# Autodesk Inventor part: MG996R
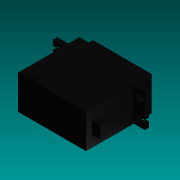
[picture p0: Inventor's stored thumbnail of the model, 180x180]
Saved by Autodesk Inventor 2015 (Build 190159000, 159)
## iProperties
Created: 2016-02
Part Number: MG996R
Material: Generic
Document SubType Name: Modeling
Designer: Rafał
Density: 1 g/cm^3
Appearance: Smooth - Black
Author: Rafał
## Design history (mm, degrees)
sketch "Sketch1"
  geometry: L1 (0, 0)-(40, 0); L2 (40, 0)-(40, 27.5); L3 (40, 27.5)-(47, 27.5); L4 (47, 27.5)-(47, 30); L5 (47, 30)-(40, 30); L6 (40, 30)-(40, 38.5); L7 (40, 38.5)-(5.5, 38.5); L8 (5.5, 38.5)-(5.5, 36); L9 (5.5, 36)-(0, 36); L10 (0, 36)-(0, 30); L11 (0, 30)-(-7, 30); L12 (-7, 30)-(-7, 27.5); L13 (-7, 27.5)-(0, 27.5); L14 (0, 27.5)-(0, 0)
  constraints: 28 end point, 8 perpendicular, 7 point on line, 2 vertical, 1 horizontal
  dimensions: "d0" = 40 distance of L1.start L1.end; "d1" = 27.5 distance of L1.end L2.end; "d2" = 7 distance of L2.end L3.end; "d3" = 2.5 distance of L3.end L4.end; "d4" = 8.5 distance of L5.end L6.end; "d5" = 34.5 distance of L6.end L7.end; "d6" = 2.5 distance of L7.end L8.end; "d7" = 7 distance of L10.end L11.end
extrude "Extrusion1" new body sketch "Sketch1" distance "d8" = 20; taper "d9" = 0 deg
sketch "Sketch2"
  geometry: L1 (7, 0)-(0, 0) reference; L2 (0, 0)-(0, -20) reference; L3 (0, 0)-(0, -20) reference; L4 (3.6, -4.6)-(0, -4.6); L5 (0, -4.6)-(0, -3.6); L6 (0, -3.6)-(3.6, -3.6); L7 (3.6, -3.6)-(3.6, -4.6); L8 (3.6, -4.6)-(0, -4.6); L9 (0, -4.6)-(0, -5.6); L10 (0, -5.6)-(3.6, -5.6); L11 (3.6, -5.6)-(3.6, -4.6); L12 (0, -10)-(54, -10); L13 (54, 0)-(54, -20) reference; L14 (27, -10)-(27, -2.45); L15 (7, 0)-(7, -20) reference; L16 (0, 0)-(7, 0); L17 (7, 0)-(7, -0.5); L18 (7, -0.5)-(0, -0.5); L19 (0, -0.5)-(0, 0); L20 (0, -14.4)-(3.6, -14.4); L21 (3.6, -14.4)-(3.6, -15.4); L22 (3.6, -16.4)-(3.6, -15.4); L23 (0, -16.4)-(3.6, -16.4); L24 (0, -15.4)-(0, -16.4); L25 (0, -15.4)-(0, -14.4); L26 (3.6, -15.4)-(0, -15.4); L27 (7, -20)-(0, -20); L28 (7, -19.5)-(0, -19.5); L29 (7, -20)-(7, -19.5); L30 (7, -20)-(7, 0); L31 (0, -19.5)-(0, -20); L32 (7, 0)-(7, -0.5); L33 (7, -19.5)-(7, -20); L34 (50.4, -14.4)-(50.4, -15.4); L35 (50.4, -16.4)-(50.4, -15.4); L36 (54, -14.4)-(50.4, -14.4); L37 (50.4, -15.4)-(54, -15.4); L38 (54, -15.4)-(54, -14.4); L39 (54, -16.4)-(50.4, -16.4); L40 (54, -15.4)-(54, -16.4); L41 (54, -19.5)-(54, -20); L42 (47, -19.5)-(54, -19.5); L43 (47, -20)-(54, -20); L44 (47, 0)-(54, 0); L45 (54, 0)-(54, -20); L46 (54, 0)-(54, -20); L47 (47, 0)-(47, -20); L48 (47, -20)-(47, 0); L49 (47, -19.5)-(47, -20); L50 (47, -20)-(47, -19.5); L51 (50.4, -4.6)-(54, -4.6); L52 (54, -4.6)-(54, -3.6); L53 (54, -3.6)-(50.4, -3.6); L54 (50.4, -3.6)-(50.4, -4.6); L55 (54, -5.6)-(50.4, -5.6); L56 (50.4, -4.6)-(54, -4.6); L57 (54, -4.6)-(54, -5.6); L58 (50.4, -5.6)-(50.4, -4.6); L59 (47, -0.5)-(54, -0.5); L60 (54, 0)-(47, 0); L61 (47, 0)-(47, -0.5); L62 (47, 0)-(47, -0.5); L63 (54, -0.5)-(54, 0); L64 (3.6, -16.4)-(0, -16.4)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; C1 r 2 at (3.6, -4.6); C2 r 2 at (3.6, -15.4); C3 r 2 at (50.4, -15.4); C4 r 2 at (50.4, -4.6)
  constraints: 132 end point, 36 symmetric about line, 10 parallel, 8 point on line, 5 horizontal, 5 perpendicular, 4 centre point, 3 midpoint, 3 vertical, 3 other
  dimensions: "d10" = 4 diameter of C1; "d11" = 4.6 distance from line of L1 L4.start; "d12" = 3.6 distance from line of L2 L4.start; "d13" = 1 distance of L4.end L5.end; "d14" = 1 distance of L9.end L8.end; "d15" = 0.5 distance of L16.end L17.end
extrude "Extrusion2" cut sketch "Sketch2" distance "d16" = 20; taper "d17" = 0 deg
sketch "Sketch3"
  geometry: 1 further point
sketch "Sketch4"
  geometry: L1 (34.5, -20)-(0, -20) reference; L2 (34.5, 0)-(34.5, -20) reference; C1 r 6.65 at (25, -10); 1 further point
  constraints: 1 centre point
  dimensions: "d18" = 13.3 diameter of C1; "d19" = 10 distance from line of L1 C1.centre; "d20" = 9.5 distance from line of L2 C1.centre
extrude "Extrusion3" join sketch "Sketch4" distance "d21" = 2; taper "d22" = 0 deg
sketch "Sketch5"
  geometry: C1 r 6.65 at (0, 0) reference; C2 r 3 at (0, 0); 1 further point
  constraints: 1 centre point, 1 coincident
  dimensions: "d23" = 6 diameter of C2
extrude "Extrusion4" join sketch "Sketch5" distance "d24" = 4; taper "d25" = 0 deg
sketch "Sketch6"
  geometry: L1 (6.5, 7.5)-(13.5, 7.5); L2 (13.5, 7.5)-(13.5, 3.5); L3 (13.5, 3.5)-(6.5, 3.5); L4 (6.5, 3.5)-(6.5, 7.5); L5 (20, 0)-(0, 0) reference; L6 (0, 0)-(0, 38.5) reference
  constraints: 8 end point, 2 parallel, 1 horizontal, 1 perpendicular
  dimensions: "d26" = 7 distance of L2.end L3.end; "d27" = 4 distance of L1.end L2.end; "d28" = 3.5 distance between parallel lines of L5 L3; "d29" = 6.5 distance between parallel lines of L6 L4
extrude "Extrusion5" join sketch "Sketch6" distance "d30" = 5; taper "d31" = 0 deg
body "Solid1"
